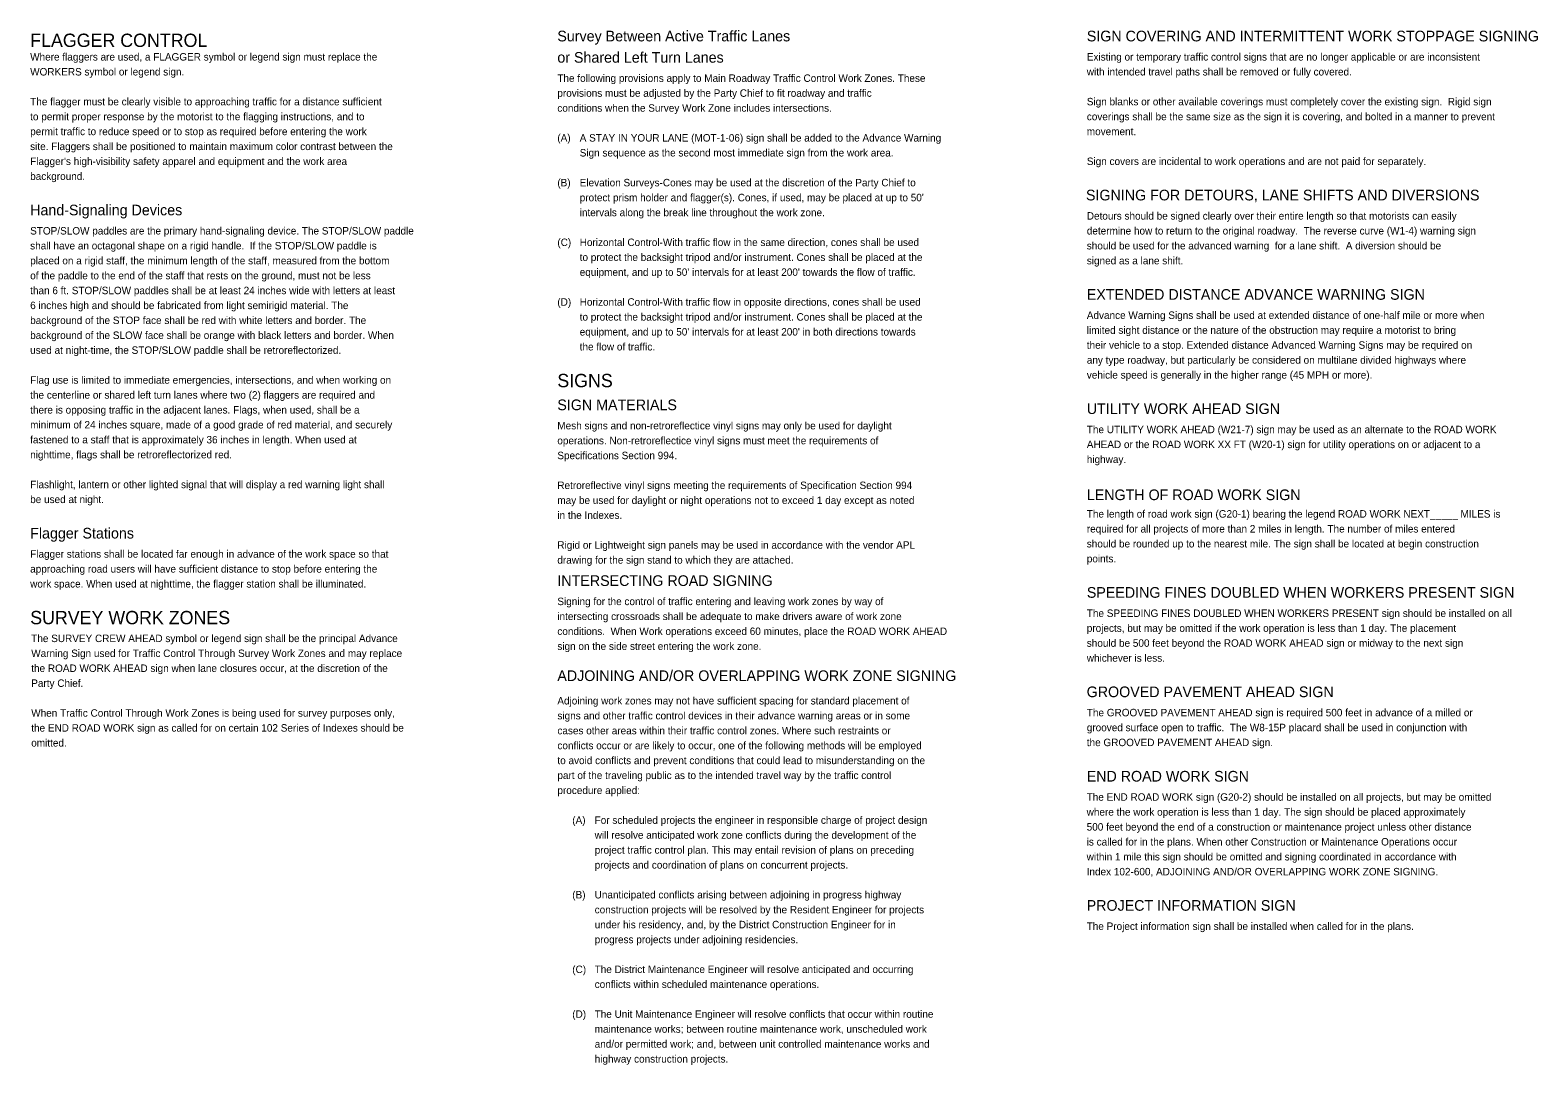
# Model space of a CAD drawing. Extents: x 10039 to 10746, y 10036 to 10521.
import ezdxf

# ---------------------------------------------------------------- set-up
doc = ezdxf.new("R2010")
doc.units = 0
doc.layers.add('TextMisc', color=7, linetype='Continuous')

msp = doc.modelspace()

# ---------------------------------------------------------------- texts
at = {"layer": 'TextMisc'}
for s, height, p in [('FLAGGER CONTROL', 6.25, (10039.11, 10513.35)), ('Survey Between Active Traffic Lanes', 5, (10286.45, 10515.97)), ('SIGN COVERING AND INTERMITTENT WORK STOPPAGE SIGNING', 5, (10534.87, 10515.97)), ('Where flaggers are used, a FLAGGER symbol or legend sign must replace the ', 3.5, (10039.11, 10506.97)), ('or Shared Left Turn Lanes', 5, (10286.45, 10505.97)), ('Existing or temporary traffic control signs that are no longer applicable or are inconsistent ', 3.5, (10534.87, 10506.97)), ('WORKERS symbol or legend sign.', 3.5, (10039.11, 10499.97)), ('The following provisions apply to Main Roadway Traffic Control Work Zones. These ', 3.5, (10286.45, 10496.97)), ('with intended travel paths shall be removed or fully covered. ', 3.5, (10534.87, 10499.97)), ('provisions must be adjusted by the Party Chief to fit roadway and traffic ', 3.5, (10286.45, 10489.97)), ('The flagger must be clearly visible to approaching traffic for a distance sufficient ', 3.5, (10039.11, 10485.97)), ('conditions when the Survey Work Zone includes intersections.', 3.5, (10286.45, 10482.97)), ('Sign blanks or other available coverings must completely cover the existing sign.  Rigid sign ', 3.5, (10534.87, 10485.97)), ('to permit proper response by the motorist to the flagging instructions, and to ', 3.5, (10039.11, 10478.97)), ('coverings shall be the same size as the sign it is covering, and bolted in a manner to prevent ', 3.5, (10534.87, 10478.97)), ('permit traffic to reduce speed or to stop as required before entering the work ', 3.5, (10039.11, 10471.97)), ('(A)', 3.5, (10286.45, 10468.97)), ('A STAY IN YOUR LANE (MOT-1-06) sign shall be added to the Advance Warning ', 3.5, (10296.95, 10468.97)), ('movement.', 3.5, (10534.87, 10471.97)), ('site. Flaggers shall be positioned to maintain maximum color contrast between the ', 3.5, (10039.11, 10464.97)), ('Sign sequence as the second most immediate sign from the work area.', 3.5, (10296.95, 10461.97)), ("Flagger's high-visibility safety apparel and equipment and the work area ", 3.5, (10039.11, 10457.97)), ('Sign covers are incidental to work operations and are not paid for separately.', 3.5, (10534.87, 10457.97)), ('background.', 3.5, (10039.11, 10450.97)), ('(B)', 3.5, (10286.45, 10447.97)), ('Elevation Surveys-Cones may be used at the discretion of the Party Chief to ', 3.5, (10296.95, 10447.97)), ("protect prism holder and flagger(s). Cones, if used, may be placed at up to 50'  ", 3.5, (10296.95, 10440.97)), ('SIGNING FOR DETOURS, LANE SHIFTS AND DIVERSIONS', 5, (10534.48, 10441.37)), ('Hand-Signaling Devices', 5, (10039.11, 10434.37)), ('intervals along the break line throughout the work zone.', 3.5, (10296.95, 10433.97)), ('Detours should be signed clearly over their entire length so that motorists can easily ', 3.5, (10534.87, 10432.37)), ('STOP/SLOW paddles are the primary hand-signaling device. The STOP/SLOW paddle ', 3.5, (10039.11, 10425.37)), ('determine how to return to the original roadway.  The reverse curve (W1-4) warning sign ', 3.5, (10534.87, 10425.37)), ('shall have an octagonal shape on a rigid handle.  If the STOP/SLOW paddle is ', 3.5, (10039.11, 10418.37)), ('(C)', 3.5, (10286.45, 10419.97)), ('Horizontal Control-With traffic flow in the same direction, cones shall be used ', 3.5, (10296.95, 10419.97)), ('should be used for the advanced warning  for a lane shift.  A diversion should be ', 3.5, (10534.87, 10418.37)), ('placed on a rigid staff, the minimum length of the staff, measured from the bottom ', 3.5, (10039.11, 10411.37)), ('to protect the backsight tripod and/or instrument. Cones shall be placed at the ', 3.5, (10296.95, 10412.97)), ('signed as a lane shift.', 3.5, (10534.87, 10411.37)), ('of the paddle to the end of the staff that rests on the ground, must not be less ', 3.5, (10039.11, 10404.37)), ("equipment, and up to 50' intervals for at least 200' towards the flow of traffic.", 3.5, (10296.95, 10405.97)), ('than 6 ft. STOP/SLOW paddles shall be at least 24 inches wide with letters at least ', 3.5, (10039.11, 10397.37)), ('EXTENDED DISTANCE ADVANCE WARNING SIGN', 5, (10534.87, 10394.76)), ('6 inches high and should be fabricated from light semirigid material. The ', 3.5, (10039.11, 10390.37)), ('(D)', 3.5, (10286.45, 10391.97)), ('Horizontal Control-With traffic flow in opposite directions, cones shall be used ', 3.5, (10296.95, 10391.97)), ('background of the STOP face shall be red with white letters and border. The ', 3.5, (10039.11, 10383.37)), ('to protect the backsight tripod and/or instrument. Cones shall be placed at the ', 3.5, (10296.95, 10384.97)), ('Advance Warning Signs shall be used at extended distance of one-half mile or more when ', 3.5, (10534.87, 10385.76)), ('background of the SLOW face shall be orange with black letters and border. When ', 3.5, (10039.11, 10376.37)), ("equipment, and up to 50' intervals for at least 200' in both directions towards ", 3.5, (10296.95, 10377.97)), ('limited sight distance or the nature of the obstruction may require a motorist to bring ', 3.5, (10534.87, 10378.76)), ('used at night-time, the STOP/SLOW paddle shall be retroreflectorized.', 3.5, (10039.11, 10369.37)), ('the flow of traffic.', 3.5, (10296.95, 10370.97)), ('their vehicle to a stop. Extended distance Advanced Warning Signs may be required on ', 3.5, (10534.87, 10371.76)), ('any type roadway, but particularly be considered on multilane divided highways where ', 3.5, (10534.87, 10364.76)), ('Flag use is limited to immediate emergencies, intersections, and when working on ', 3.5, (10039.11, 10355.37)), ('SIGNS', 6.25, (10286.45, 10353.74)), ('vehicle speed is generally in the higher range (45 MPH or more).', 3.5, (10534.87, 10357.76)), ('the centerline or shared left turn lanes where two (2) flaggers are required and ', 3.5, (10039.11, 10348.37)), ('there is opposing traffic in the adjacent lanes. Flags, when used, shall be a ', 3.5, (10039.11, 10341.37)), ('SIGN MATERIALS', 5, (10286.45, 10342.96)), ('UTILITY WORK AHEAD SIGN', 5, (10534.87, 10341.16)), ('minimum of 24 inches square, made of a good grade of red material, and securely ', 3.5, (10039.11, 10334.37)), ('Mesh signs and non-retroreflectice vinyl signs may only be used for daylight ', 3.5, (10286.45, 10333.96)), ('The UTILITY WORK AHEAD (W21-7) sign may be used as an alternate to the ROAD WORK ', 3.5, (10534.87, 10332.16)), ('fastened to a staff that is approximately 36 inches in length. When used at ', 3.5, (10039.11, 10327.37)), ('operations. Non-retroreflectice vinyl signs must meet the requirements of ', 3.5, (10286.45, 10326.96)), ('AHEAD or the ROAD WORK XX FT (W20-1) sign for utility operations on or adjacent to a ', 3.5, (10534.87, 10325.16)), ('nighttime, flags shall be retroreflectorized red.', 3.5, (10039.11, 10320.37)), ('Specifications Section 994.', 3.5, (10286.45, 10319.96)), ('highway.', 3.5, (10534.87, 10318.16)), ('Flashlight, lantern or other lighted signal that will display a red warning light shall ', 3.5, (10039.11, 10306.37)), ('Retroreflective vinyl signs meeting the requirements of Specification Section 994 ', 3.5, (10286.45, 10305.96)), ('be used at night.', 3.5, (10039.11, 10299.37)), ('may be used for daylight or night operations not to exceed 1 day except as noted ', 3.5, (10286.45, 10298.96)), ('LENGTH OF ROAD WORK SIGN', 5, (10534.87, 10300.76)), ('in the Indexes.', 3.5, (10286.45, 10291.96)), ('The length of road work sign (G20-1) bearing the legend ROAD WORK NEXT_____ MILES is ', 3.5, (10534.87, 10292.56)), ('Flagger Stations', 5, (10039.11, 10282.76)), ('required for all projects of more than 2 miles in length. The number of miles entered ', 3.5, (10534.87, 10285.56)), ('Rigid or Lightweight sign panels may be used in accordance with the vendor APL ', 3.5, (10286.45, 10277.96)), ('should be rounded up to the nearest mile. The sign shall be located at begin construction ', 3.5, (10534.87, 10278.56)), ('Flagger stations shall be located far enough in advance of the work space so that ', 3.5, (10039.11, 10273.76)), ('drawing for the sign stand to which they are attached.', 3.5, (10286.45, 10270.96)), ('points.', 3.5, (10534.87, 10271.56)), ('approaching road users will have sufficient distance to stop before entering the ', 3.5, (10039.11, 10266.76)), ('INTERSECTING ROAD SIGNING', 5, (10286.45, 10260.5)), ('work space. When used at nighttime, the flagger station shall be illuminated.', 3.5, (10039.11, 10259.76)), ('SPEEDING FINES DOUBLED WHEN WORKERS PRESENT SIGN', 5, (10534.87, 10254.96)), ('Signing for the control of traffic entering and leaving work zones by way of ', 3.5, (10286.45, 10251.5)), ('SURVEY WORK ZONES', 6.25, (10039.11, 10242.54)), ('intersecting crossroads shall be adequate to make drivers aware of work zone ', 3.5, (10286.45, 10244.5)), ('The SPEEDING FINES DOUBLED WHEN WORKERS PRESENT sign should be installed on all ', 3.5, (10534.87, 10245.96)), ('The SURVEY CREW AHEAD symbol or legend sign shall be the principal Advance ', 3.5, (10039.61, 10234.16)), ('conditions.  When Work operations exceed 60 minutes, place the ROAD WORK AHEAD ', 3.5, (10286.45, 10237.5)), ('projects, but may be omitted if the work operation is less than 1 day. The placement ', 3.5, (10534.87, 10238.96)), ('Warning Sign used for Traffic Control Through Survey Work Zones and may replace ', 3.5, (10039.61, 10227.16)), ('sign on the side street entering the work zone.', 3.5, (10286.45, 10230.5)), ('should be 500 feet beyond the ROAD WORK AHEAD sign or midway to the next sign ', 3.5, (10534.87, 10231.96)), ('the ROAD WORK AHEAD sign when lane closures occur, at the discretion of the ', 3.5, (10039.61, 10220.16)), ('whichever is less. ', 3.5, (10534.87, 10224.96)), ('Party Chief. ', 3.5, (10039.61, 10213.16)), ('ADJOINING AND/OR OVERLAPPING WORK ZONE SIGNING', 5, (10286.45, 10215.9)), ('Adjoining work zones may not have sufficient spacing for standard placement of ', 3.5, (10286.45, 10204.9)), ('GROOVED PAVEMENT AHEAD SIGN', 5, (10534.81, 10208.33)), ('When Traffic Control Through Work Zones is being used for survey purposes only, ', 3.5, (10039.61, 10199.16)), ('signs and other traffic control devices in their advance warning areas or in some ', 3.5, (10286.48, 10197.9)), ('The GROOVED PAVEMENT AHEAD sign is required 500 feet in advance of a milled or ', 3.5, (10534.87, 10199.35)), ('the END ROAD WORK sign as called for on certain 102 Series of Indexes should be ', 3.5, (10039.61, 10192.16)), ('cases other areas within their traffic control zones. Where such restraints or ', 3.5, (10286.48, 10190.9)), ('grooved surface open to traffic.  The W8-15P placard shall be used in conjunction with ', 3.5, (10534.87, 10192.35)), ('omitted.', 3.5, (10039.61, 10185.16)), ('conflicts occur or are likely to occur, one of the following methods will be employed ', 3.5, (10286.48, 10183.9)), ('the GROOVED PAVEMENT AHEAD sign.', 3.5, (10534.87, 10185.35)), ('to avoid conflicts and prevent conditions that could lead to misunderstanding on the ', 3.5, (10286.48, 10176.9)), ('part of the traveling public as to the intended travel way by the traffic control ', 3.5, (10286.48, 10169.9)), ('END ROAD WORK SIGN', 5, (10534.81, 10168.73)), ('procedure applied:', 3.5, (10286.48, 10162.9)), ('The END ROAD WORK sign (G20-2) should be installed on all projects, but may be omitted ', 3.5, (10534.81, 10159.73)), ('(A)', 3.5, (10293.45, 10148.9)), ('For scheduled projects the engineer in responsible charge of project design ', 3.5, (10303.95, 10148.9)), ('where the work operation is less than 1 day. The sign should be placed approximately ', 3.5, (10534.81, 10152.73)), ('will resolve anticipated work zone conflicts during the development of the ', 3.5, (10303.98, 10141.9)), ('500 feet beyond the end of a construction or maintenance project unless other distance ', 3.5, (10534.81, 10145.73)), ('project traffic control plan. This may entail revision of plans on preceding ', 3.5, (10303.98, 10134.9)), ('is called for in the plans. When other Construction or Maintenance Operations occur ', 3.5, (10534.81, 10138.73)), ('projects and coordination of plans on concurrent projects.', 3.5, (10303.98, 10127.9)), ('within 1 mile this sign should be omitted and signing coordinated in accordance with ', 3.5, (10534.81, 10131.73)), ('Index 102-600, ADJOINING AND/OR OVERLAPPING WORK ZONE SIGNING.', 3.5, (10534.81, 10124.73)), ('(B)', 3.5, (10293.45, 10113.9)), ('Unanticipated conflicts arising between adjoining in progress highway ', 3.5, (10303.95, 10113.9)), ('construction projects will be resolved by the Resident Engineer for projects ', 3.5, (10303.98, 10106.9)), ('PROJECT INFORMATION SIGN', 5, (10534.81, 10108.13)), ('under his residency, and, by the District Construction Engineer for in ', 3.5, (10303.98, 10099.9)), ('The Project information sign shall be installed when called for in the plans.', 3.5, (10534.81, 10099.13)), ('progress projects under adjoining residencies.', 3.5, (10303.98, 10092.9)), ('(C)', 3.5, (10293.45, 10078.9)), ('The District Maintenance Engineer will resolve anticipated and occurring ', 3.5, (10303.95, 10078.9)), ('conflicts within scheduled maintenance operations.', 3.5, (10303.98, 10071.9)), ('(D)', 3.5, (10293.45, 10057.9)), ('The Unit Maintenance Engineer will resolve conflicts that occur within routine ', 3.5, (10303.95, 10057.9)), ('maintenance works; between routine maintenance work, unscheduled work ', 3.5, (10303.98, 10050.9)), ('and/or permitted work; and, between unit controlled maintenance works and ', 3.5, (10303.98, 10043.9)), ('highway construction projects.', 3.5, (10303.98, 10036.9))]:
    msp.add_text(s, height=height, dxfattribs=at).set_placement(p)

doc.saveas('drawing.dxf')
